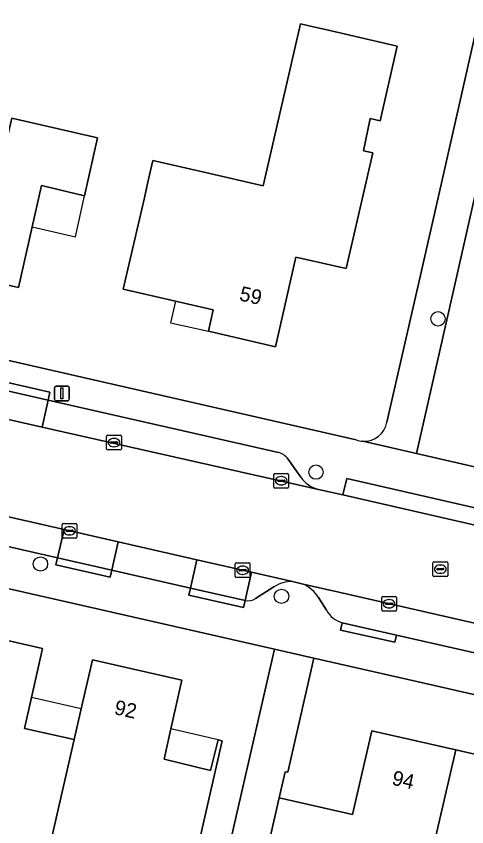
# Model space of a CAD drawing. Extents: x 159626 to 160723, y 388173 to 389416.
# Drawn here: x 160209.5 to 160240.2, y 388707.3 to 388762.4 of the extents above; entities that cross this region are included whole.
import ezdxf

# ---------------------------------------------------------------- set-up
doc = ezdxf.new("R2010")
doc.units = 0
for name, color, linetype in [('IMGEO_Boom', 7, 'Continuous'), ('IMGEO_Erf', 7, 'Continuous'), ('IMGEO_Kolk', 7, 'Continuous'), ('IMGEO_Lichtmast', 7, 'Continuous'), ('IMGEO_Pand', 7, 'Continuous'), ('IMGEO_Pand_nummerreeks', 7, 'Continuous'), ('IMGEO_Pand_overbouw', 7, 'Continuous'), ('IMGEO_Parkeervlak_open', 7, 'Continuous'), ('IMGEO_Rijbaan_lokaal_gesloten', 7, 'Continuous'), ('IMGEO_Rijbaan_lokaal_open', 7, 'Continuous'), ('IMGEO_Rioolput', 7, 'Continuous'), ('IMGEO_Voetpad_open', 7, 'Continuous')]:
    doc.layers.add(name, color=color, linetype=linetype)

msp = doc.modelspace()

# ---------------------------------------------------------------- linework, layer by layer
at = {"layer": 'IMGEO_Boom'}
for centre in [(160238.202, 388741.85), (160229.904, 388731.42), (160211.166, 388725.17), (160227.558, 388722.969)]:
    msp.add_circle(centre, 0.489, dxfattribs=at)
at = {"layer": 'IMGEO_Erf'}
for points in [[(160234.722, 388734.828), (160237.013, 388744.82), (160238.186, 388750), (160246.535, 388786.875)], [(160186.662, 388744.107), (160232.634, 388733.614)], [(160223.367, 388703.114), (160224.3, 388707.209), (160227.072, 388719.379), (160183.407, 388729.319), (160181.681, 388729.655), (160179.863, 388729.928)], [(160205.232, 388720.803), (160211.309, 388719.424), (160210.553, 388716.084), (160210.078, 388713.984), (160213.45, 388713.222), (160213.931, 388715.318), (160214.697, 388718.656), (160220.785, 388717.266), (160220.025, 388713.963), (160219.569, 388711.883), (160222.739, 388711.12), (160223.244, 388713.208), (160223.525, 388713.137), (160221.525, 388704.392)], [(160321.781, 388697.748), (160237.27, 388717.058), (160229.749, 388718.77), (160227.986, 388710.997), (160227.804, 388711.038), (160227.4, 388709.263), (160232.392, 388708.126), (160232.796, 388709.901), (160233.69, 388713.83), (160239.411, 388712.521), (160245.1, 388711.22), (160244.166, 388707.186)]]:
    msp.add_lwpolyline(points, dxfattribs=at)
for points in [[(160218.212, 388750), (160218.478, 388751.154), (160218.816, 388752.624), (160222.38, 388751.804), (160226.312, 388750.898), (160228.85, 388761.918), (160229.622, 388761.74), (160230.554, 388761.525), (160235.426, 388760.403), (160234.269, 388755.324), (160233.592, 388755.48), (160233.139, 388753.282), (160233.77, 388753.152), (160233.045, 388750), (160231.959, 388745.281), (160228.536, 388746.055), (160227.15, 388739.949), (160222.597, 388741), (160222.907, 388742.466), (160220.359, 388743.056), (160216.801, 388743.87)], [(160201.708, 388754.434), (160205.402, 388753.588), (160205.473, 388753.899), (160208.679, 388753.166), (160209.212, 388755.497), (160215.042, 388754.164), (160214.165, 388750.227), (160211.235, 388750.923), (160210.6, 388748.099), (160209.665, 388743.979), (160203.522, 388745.371), (160203.899, 388747.019), (160200.205, 388747.865), (160200.693, 388750)]]:
    msp.add_lwpolyline(points, close=True, dxfattribs=at)
for centre, radius, start, end in [((160233.177, 388735.083), 1.566, 266.9986, 350.6382), ((160233.176, 388735.078), 1.561, 249.6829, 267.0288)]:
    msp.add_arc(centre, radius, start, end, dxfattribs=at)
at = {"layer": 'IMGEO_Kolk'}
for p, q in [((160215.667, 388733.003), (160215.667, 388733.855)), ((160215.742, 388733.929), (160216.594, 388733.929)), ((160216.155, 388733.709), (160216.18, 388733.709)), ((160216.668, 388733.855), (160216.668, 388733.003)), ((160215.926, 388733.423), (160215.926, 388733.435)), ((160216.364, 388733.386), (160215.966, 388733.386)), ((160215.969, 388733.472), (160216.367, 388733.472)), ((160216.178, 388733.149), (160216.153, 388733.149)), ((160216.41, 388733.435), (160216.41, 388733.423)), ((160216.594, 388732.929), (160215.742, 388732.929)), ((160227.039, 388730.408), (160227.039, 388731.26)), ((160227.114, 388731.334), (160227.966, 388731.334)), ((160227.298, 388730.828), (160227.298, 388730.84)), ((160227.341, 388730.877), (160227.739, 388730.877)), ((160227.527, 388731.114), (160227.552, 388731.114)), ((160227.782, 388730.84), (160227.782, 388730.828)), ((160228.04, 388731.26), (160228.04, 388730.408)), ((160227.966, 388730.334), (160227.114, 388730.334)), ((160227.736, 388730.791), (160227.338, 388730.791)), ((160227.55, 388730.554), (160227.525, 388730.554)), ((160212.642, 388727.001), (160212.642, 388727.853)), ((160212.717, 388727.927), (160213.569, 388727.927)), ((160213.13, 388727.707), (160213.155, 388727.707)), ((160213.643, 388727.853), (160213.643, 388727.001)), ((160212.901, 388727.421), (160212.901, 388727.433)), ((160213.339, 388727.384), (160212.941, 388727.384)), ((160212.944, 388727.47), (160213.342, 388727.47)), ((160213.153, 388727.147), (160213.128, 388727.147)), ((160213.385, 388727.433), (160213.385, 388727.421)), ((160213.569, 388726.927), (160212.717, 388726.927)), ((160224.414, 388724.317), (160224.414, 388725.169)), ((160224.489, 388725.243), (160225.341, 388725.243)), ((160224.716, 388724.786), (160225.114, 388724.786)), ((160224.902, 388725.023), (160224.927, 388725.023)), ((160225.415, 388725.169), (160225.415, 388724.317)), ((160225.341, 388724.243), (160224.489, 388724.243)), ((160224.673, 388724.737), (160224.673, 388724.749)), ((160225.111, 388724.7), (160224.713, 388724.7)), ((160224.925, 388724.463), (160224.9, 388724.463)), ((160225.157, 388724.749), (160225.157, 388724.737)), ((160234.37, 388722.042), (160234.37, 388722.894)), ((160234.445, 388722.968), (160235.297, 388722.968)), ((160234.858, 388722.748), (160234.883, 388722.748)), ((160235.371, 388722.894), (160235.371, 388722.042)), ((160234.629, 388722.462), (160234.629, 388722.474)), ((160235.067, 388722.425), (160234.669, 388722.425)), ((160234.672, 388722.511), (160235.07, 388722.511)), ((160234.881, 388722.188), (160234.856, 388722.188)), ((160235.113, 388722.474), (160235.113, 388722.462)), ((160235.297, 388721.968), (160234.445, 388721.968))]:
    msp.add_line(p, q, dxfattribs=at)
for points in [[(160215.667, 388733.003), (160215.667, 388733.855)], [(160215.742, 388733.929), (160216.594, 388733.929)], [(160216.668, 388733.855), (160216.668, 388733.003)], [(160216.594, 388732.929), (160215.742, 388732.929)], [(160227.039, 388730.408), (160227.039, 388731.26)], [(160227.114, 388731.334), (160227.966, 388731.334)], [(160228.04, 388731.26), (160228.04, 388730.408)], [(160227.966, 388730.334), (160227.114, 388730.334)], [(160212.642, 388727.001), (160212.642, 388727.853)], [(160212.717, 388727.927), (160213.569, 388727.927)], [(160213.643, 388727.853), (160213.643, 388727.001)], [(160213.569, 388726.927), (160212.717, 388726.927)], [(160224.414, 388724.317), (160224.414, 388725.169)], [(160224.489, 388725.243), (160225.341, 388725.243)], [(160225.415, 388725.169), (160225.415, 388724.317)], [(160225.341, 388724.243), (160224.489, 388724.243)], [(160234.37, 388722.042), (160234.37, 388722.894)], [(160234.445, 388722.968), (160235.297, 388722.968)], [(160235.371, 388722.894), (160235.371, 388722.042)], [(160235.297, 388721.968), (160234.445, 388721.968)]]:
    msp.add_lwpolyline(points, dxfattribs=at)
for centre, radius, start, end in [((160215.744, 388733.853), 0.0765, 91.552, 178.448), ((160215.744, 388733.853), 0.0765, 91.552, 178.448), ((160216.592, 388733.853), 0.0765, 1.552, 88.448), ((160216.592, 388733.853), 0.0765, 1.552, 88.448), ((160215.966, 388733.432), 0.0403, 85.8775, 175.7526), ((160215.963, 388733.422), 0.0366, 178.938, 274.7102), ((160216.367, 388733.429), 0.043, 264.8664, 352.4533), ((160216.371, 388733.434), 0.0386, 1.7309, 96.639), ((160215.744, 388733.005), 0.0765, 181.552, 268.448), ((160215.744, 388733.005), 0.0765, 181.552, 268.448), ((160216.592, 388733.005), 0.0765, 271.552, 358.448), ((160216.592, 388733.005), 0.0765, 271.552, 358.448), ((160227.116, 388731.258), 0.0765, 91.552, 178.448), ((160227.116, 388731.258), 0.0765, 91.552, 178.448), ((160227.338, 388730.837), 0.0403, 85.8775, 175.7526), ((160227.335, 388730.827), 0.0366, 178.938, 274.7102), ((160227.739, 388730.834), 0.043, 264.8664, 352.4533), ((160227.743, 388730.839), 0.0386, 1.7309, 96.639), ((160227.964, 388731.258), 0.0765, 1.552, 88.448), ((160227.964, 388731.258), 0.0765, 1.552, 88.448), ((160227.116, 388730.41), 0.0765, 181.552, 268.448), ((160227.116, 388730.41), 0.0765, 181.552, 268.448), ((160227.964, 388730.41), 0.0765, 271.552, 358.448), ((160227.964, 388730.41), 0.0765, 271.552, 358.448), ((160212.719, 388727.851), 0.0765, 91.552, 178.448), ((160212.719, 388727.851), 0.0765, 91.552, 178.448), ((160213.567, 388727.851), 0.0765, 1.552, 88.448), ((160213.567, 388727.851), 0.0765, 1.552, 88.448), ((160212.719, 388727.003), 0.0765, 181.552, 268.448), ((160212.719, 388727.003), 0.0765, 181.552, 268.448), ((160212.941, 388727.43), 0.0403, 85.8775, 175.7526), ((160212.938, 388727.42), 0.0366, 178.938, 274.7102), ((160213.342, 388727.427), 0.043, 264.8664, 352.4533), ((160213.346, 388727.432), 0.0386, 1.7309, 96.639), ((160213.567, 388727.003), 0.0765, 271.552, 358.448), ((160213.567, 388727.003), 0.0765, 271.552, 358.448), ((160224.491, 388725.167), 0.0765, 91.552, 178.448), ((160224.491, 388725.167), 0.0765, 91.552, 178.448), ((160224.713, 388724.746), 0.0403, 85.8775, 175.7526), ((160225.118, 388724.748), 0.0386, 1.7309, 96.639), ((160225.339, 388725.167), 0.0765, 1.552, 88.448), ((160225.339, 388725.167), 0.0765, 1.552, 88.448), ((160224.491, 388724.319), 0.0765, 181.552, 268.448), ((160224.491, 388724.319), 0.0765, 181.552, 268.448), ((160224.71, 388724.736), 0.0366, 178.938, 274.7102), ((160225.114, 388724.743), 0.043, 264.8664, 352.4533), ((160225.339, 388724.319), 0.0765, 271.552, 358.448), ((160225.339, 388724.319), 0.0765, 271.552, 358.448), ((160234.447, 388722.892), 0.0765, 91.552, 178.448), ((160234.447, 388722.892), 0.0765, 91.552, 178.448), ((160235.295, 388722.892), 0.0765, 1.552, 88.448), ((160235.295, 388722.892), 0.0765, 1.552, 88.448), ((160234.447, 388722.044), 0.0765, 181.552, 268.448), ((160234.447, 388722.044), 0.0765, 181.552, 268.448), ((160234.669, 388722.471), 0.0403, 85.8775, 175.7526), ((160234.666, 388722.461), 0.0366, 178.938, 274.7102), ((160235.07, 388722.468), 0.043, 264.8664, 352.4533), ((160235.074, 388722.473), 0.0386, 1.7309, 96.639), ((160235.295, 388722.044), 0.0765, 271.552, 358.448), ((160235.295, 388722.044), 0.0765, 271.552, 358.448)]:
    msp.add_arc(centre, radius, start, end, dxfattribs=at)
for centre, major_axis, ratio, start_param, end_param in [((160216.154, 388733.429), (-0.387, 0.002), 0.722429, 4.712389, 7.853982), ((160216.179, 388733.429), (-0.39, 0.002), 0.717154, 1.570796, 4.712389), ((160227.526, 388730.834), (-0.387, 0.002), 0.722429, 4.712389, 7.853982), ((160227.551, 388730.834), (-0.39, 0.002), 0.717154, 1.570796, 4.712389), ((160213.129, 388727.427), (-0.387, 0.002), 0.722429, 4.712389, 7.853982), ((160213.154, 388727.427), (-0.39, 0.002), 0.717154, 1.570796, 4.712389), ((160224.901, 388724.743), (-0.387, 0.002), 0.722429, 4.712389, 7.853982), ((160224.926, 388724.743), (-0.39, 0.002), 0.717154, 1.570796, 4.712389), ((160234.857, 388722.468), (-0.387, 0.002), 0.722429, 4.712389, 7.853982), ((160234.882, 388722.468), (-0.39, 0.002), 0.717154, 1.570796, 4.712389)]:
    msp.add_ellipse(centre, major_axis=major_axis, ratio=ratio, start_param=start_param, end_param=end_param, dxfattribs=at)
at = {"layer": 'IMGEO_Lichtmast'}
for p, q in [((160212.127, 388736.374), (160212.127, 388737.174)), ((160212.127, 388737.174), (160212.127, 388736.374)), ((160212.227, 388737.274), (160213.017, 388737.274)), ((160213.017, 388737.274), (160212.227, 388737.274)), ((160213.117, 388737.174), (160213.117, 388736.374)), ((160213.117, 388736.374), (160213.117, 388737.174)), ((160213.017, 388736.274), (160212.227, 388736.274)), ((160212.227, 388736.274), (160213.017, 388736.274))]:
    msp.add_line(p, q, dxfattribs=at)
msp.add_lwpolyline([(160212.547, 388737.149), (160212.697, 388737.149), (160212.697, 388736.399), (160212.547, 388736.399), (160212.547, 388737.149)], dxfattribs=at)
for centre, start, end in [((160212.227, 388737.174), 90, 180), ((160212.227, 388737.174), 90, 180), ((160213.017, 388737.174), 0, 90), ((160213.017, 388737.174), 360, 90), ((160212.227, 388736.374), 180, 270), ((160212.227, 388736.374), 180, 270), ((160213.017, 388736.374), 270, 0), ((160213.017, 388736.374), 270, 0)]:
    msp.add_arc(centre, 0.1, start, end, dxfattribs=at)
at = {"layer": 'IMGEO_Pand'}
for points in [[(160233.77, 388753.152), (160233.139, 388753.282), (160233.592, 388755.48), (160234.269, 388755.324), (160235.426, 388760.403), (160230.554, 388761.525), (160229.622, 388761.74), (160228.85, 388761.918), (160226.312, 388750.898), (160222.38, 388751.804), (160218.816, 388752.624), (160218.478, 388751.154), (160218.212, 388750), (160216.801, 388743.87), (160220.359, 388743.056), (160222.907, 388742.466), (160222.597, 388741), (160227.15, 388739.949), (160228.536, 388746.055), (160231.959, 388745.281), (160233.045, 388750)], [(160214.165, 388750.227), (160215.042, 388754.164), (160209.212, 388755.497), (160208.679, 388753.166), (160205.473, 388753.899), (160205.402, 388753.588), (160201.708, 388754.434), (160200.693, 388750), (160200.205, 388747.865), (160203.899, 388747.019), (160203.522, 388745.371), (160209.665, 388743.979), (160210.6, 388748.099), (160211.235, 388750.923)], [(160213.45, 388713.222), (160210.078, 388713.984), (160210.553, 388716.084), (160211.309, 388719.424), (160205.232, 388720.803), (160204.479, 388717.507), (160203.99, 388715.368), (160203.012, 388711.086), (160203.159, 388711.052), (160206.774, 388710.226), (160206.239, 388707.888), (160205.731, 388705.666), (160208.592, 388701.238), (160208.943, 388701.124), (160209.218, 388702.195), (160210.98, 388701.792), (160211.459, 388703.887), (160212.026, 388706.564), (160211.928, 388706.586)], [(160223.525, 388713.137), (160223.244, 388713.208), (160222.739, 388711.12), (160219.569, 388711.883), (160220.025, 388713.963), (160220.785, 388717.266), (160214.697, 388718.656), (160213.931, 388715.318), (160213.45, 388713.222), (160211.928, 388706.586), (160212.026, 388706.564), (160211.459, 388703.887), (160215.202, 388703.03), (160215.813, 388705.698), (160216.651, 388705.507), (160221.525, 388704.392)], [(160239.411, 388712.521), (160233.69, 388713.83), (160232.796, 388709.901), (160232.392, 388708.126), (160227.4, 388709.263), (160225.341, 388700.225), (160231.578, 388698.805), (160232.916, 388699.692), (160233.152, 388700.775), (160233.73, 388703.316), (160237.101, 388702.549)], [(160237.101, 388702.549), (160240.482, 388701.78), (160239.904, 388699.239), (160245.641, 388697.934), (160247.535, 388706.406), (160244.166, 388707.186), (160245.1, 388711.22), (160239.411, 388712.521)]]:
    msp.add_lwpolyline(points, close=True, dxfattribs=at)
at = {"layer": 'IMGEO_Pand_overbouw'}
for points in [[(160214.165, 388750.227), (160211.235, 388750.923), (160210.6, 388748.099), (160213.544, 388747.439)], [(160220.359, 388743.056), (160220.005, 388741.575), (160222.597, 388741), (160222.907, 388742.466)], [(160213.931, 388715.318), (160210.553, 388716.084), (160210.078, 388713.984), (160213.45, 388713.222)], [(160223.244, 388713.208), (160220.025, 388713.963), (160219.569, 388711.883), (160222.739, 388711.12)]]:
    msp.add_lwpolyline(points, close=True, dxfattribs=at)
at = {"layer": 'IMGEO_Parkeervlak_open'}
for points in [[(160211.696, 388736.31), (160207.987, 388737.153), (160207.553, 388735.321), (160211.28, 388734.481)], [(160212.768, 388727.514), (160207.181, 388728.788), (160206.742, 388726.865), (160212.324, 388725.595)], [(160216.45, 388726.674), (160212.768, 388727.514), (160212.324, 388725.595), (160216.011, 388724.754)], [(160221.807, 388725.453), (160216.45, 388726.674), (160216.011, 388724.754), (160216.013, 388724.754), (160221.37, 388723.533)], [(160225.52, 388724.606), (160221.807, 388725.453), (160221.37, 388723.533), (160225.081, 388722.687)]]:
    msp.add_lwpolyline(points, close=True, dxfattribs=at)
for points in [[(160211.696, 388736.31), (160211.28, 388734.481), (160230.065, 388730.247)], [(160227.347, 388732.748), (160211.696, 388736.31)], [(160228.876, 388731.081), (160227.997, 388732.315)], [(160228.297, 388723.973), (160225.52, 388724.606), (160225.081, 388722.687)], [(160231.462, 388723.248), (160229.021, 388723.807)], [(160225.792, 388722.823), (160227.036, 388723.608)], [(160231.681, 388721.166), (160235.38, 388720.33), (160246.805, 388717.749), (160247.241, 388719.647), (160231.462, 388723.248)], [(160230.077, 388722.88), (160230.621, 388722.026)]]:
    msp.add_lwpolyline(points, dxfattribs=at)
for centre, radius, start, end in [((160227.109, 388731.687), 1.088, 35.2876, 77.373), ((160230.538, 388732.186), 1.996, 213.6201, 256.286), ((160228.267, 388721.716), 2.257, 89.2381, 123.0483), ((160228.052, 388721.638), 2.376, 31.523, 65.921), ((160225.256, 388723.698), 1.026, 260.1678, 301.4897), ((160232.191, 388722.878), 1.786, 208.4784, 253.4154)]:
    msp.add_arc(centre, radius, start, end, dxfattribs=at)
at = {"layer": 'IMGEO_Rijbaan_lokaal_gesloten'}
msp.add_lwpolyline([(160244.089, 388727.051), (160231.719, 388729.878), (160230.065, 388730.247), (160211.28, 388734.481), (160207.553, 388735.321), (160192.873, 388738.63), (160187.729, 388739.79), (160186.385, 388733.53), (160194.236, 388731.738), (160197.887, 388730.906), (160203.464, 388729.635), (160207.181, 388728.788), (160212.768, 388727.514), (160216.45, 388726.674), (160221.807, 388725.453), (160225.52, 388724.606), (160228.297, 388723.973), (160229.021, 388723.807), (160231.462, 388723.248), (160247.241, 388719.647)], dxfattribs=at)
at = {"layer": 'IMGEO_Rijbaan_lokaal_open'}
msp.add_lwpolyline([(160252.345, 388777.916), (160247.25, 388779.082), (160240.666, 388750), (160239.37, 388744.275), (160236.732, 388732.697), (160241.762, 388731.537), (160244.339, 388742.931), (160245.957, 388750)], close=True, dxfattribs=at)
at = {"layer": 'IMGEO_Rioolput'}
for p, q in [((160237.932, 388725.32), (160238.784, 388725.32)), ((160237.857, 388724.394), (160237.857, 388725.246)), ((160238.116, 388724.814), (160238.116, 388724.826)), ((160238.554, 388724.777), (160238.156, 388724.777)), ((160238.159, 388724.863), (160238.557, 388724.863)), ((160238.345, 388725.1), (160238.37, 388725.1)), ((160238.6, 388724.826), (160238.6, 388724.814)), ((160238.858, 388725.246), (160238.858, 388724.394)), ((160238.784, 388724.32), (160237.932, 388724.32)), ((160238.368, 388724.54), (160238.343, 388724.54))]:
    msp.add_line(p, q, dxfattribs=at)
for points in [[(160237.932, 388725.32), (160238.784, 388725.32)], [(160237.857, 388724.394), (160237.857, 388725.246)], [(160238.858, 388725.246), (160238.858, 388724.394)], [(160238.784, 388724.32), (160237.932, 388724.32)]]:
    msp.add_lwpolyline(points, dxfattribs=at)
for centre, radius, start, end in [((160237.934, 388725.244), 0.0765, 91.552, 178.448), ((160237.934, 388725.244), 0.0765, 91.552, 178.448), ((160238.782, 388725.244), 0.0765, 1.552, 88.448), ((160238.782, 388725.244), 0.0765, 1.552, 88.448), ((160238.156, 388724.823), 0.0403, 85.8775, 175.7526), ((160238.153, 388724.813), 0.0366, 178.938, 274.7102), ((160238.557, 388724.82), 0.043, 264.8664, 352.4533), ((160238.561, 388724.825), 0.0386, 1.7309, 96.639), ((160237.934, 388724.396), 0.0765, 181.552, 268.448), ((160237.934, 388724.396), 0.0765, 181.552, 268.448), ((160238.782, 388724.396), 0.0765, 271.552, 358.448), ((160238.782, 388724.396), 0.0765, 271.552, 358.448)]:
    msp.add_arc(centre, radius, start, end, dxfattribs=at)
for centre, major_axis, ratio, start_param, end_param in [((160238.344, 388724.82), (-0.387, 0.002), 0.722429, 4.712389, 7.853982), ((160238.369, 388724.82), (-0.39, 0.002), 0.717154, 1.570796, 4.712389)]:
    msp.add_ellipse(centre, major_axis=major_axis, ratio=ratio, start_param=start_param, end_param=end_param, dxfattribs=at)
at = {"layer": 'IMGEO_Voetpad_open'}
for points in [[(160246.535, 388786.875), (160238.186, 388750), (160237.013, 388744.82), (160234.722, 388734.828)], [(160233.095, 388733.519), (160236.732, 388732.697), (160239.37, 388744.275), (160240.666, 388750), (160247.25, 388779.082)], [(160232.634, 388733.614), (160186.662, 388744.107)], [(160187.322, 388741.856), (160188.156, 388741.666), (160188.276, 388742.193), (160193.434, 388741.012), (160193.311, 388740.493), (160207.987, 388737.153), (160208.117, 388737.698), (160211.81, 388736.85), (160211.696, 388736.31), (160227.347, 388732.748)], [(160236.732, 388732.697), (160233.095, 388733.519)], [(160225.081, 388722.687), (160224.97, 388722.2), (160221.258, 388723.045), (160221.37, 388723.533), (160216.013, 388724.754), (160215.9, 388724.267), (160212.213, 388725.108), (160212.324, 388725.595), (160206.742, 388726.865), (160206.631, 388726.377), (160202.914, 388727.223), (160203.025, 388727.71), (160197.447, 388728.98), (160197.336, 388728.492), (160193.643, 388729.33), (160193.754, 388729.817), (160191.078, 388730.424), (160181.115, 388732.553)], [(160230.065, 388730.247), (160231.719, 388729.878), (160232.003, 388730.992), (160244.371, 388728.159), (160246.042, 388730.589), (160241.762, 388731.537), (160236.732, 388732.697)], [(160227.997, 388732.315), (160228.876, 388731.081)], [(160174.144, 388731.086), (160179.863, 388729.928), (160181.681, 388729.655), (160183.407, 388729.319), (160227.072, 388719.379), (160229.749, 388718.77), (160237.27, 388717.058), (160321.781, 388697.748), (160325.989, 388696.807)], [(160229.021, 388723.807), (160228.297, 388723.973)], [(160227.036, 388723.608), (160225.792, 388722.823)], [(160230.621, 388722.026), (160230.077, 388722.88)], [(160317.901, 388701.629), (160307.972, 388703.897), (160307.871, 388703.42), (160301.244, 388704.929), (160301.333, 388705.414), (160289.592, 388708.096), (160289.502, 388707.619), (160282.881, 388709.142), (160282.993, 388709.603), (160271.843, 388712.15), (160271.74, 388711.669), (160265.096, 388713.191), (160265.213, 388713.665), (160253.461, 388716.246), (160253.351, 388715.758), (160246.695, 388717.262), (160246.805, 388717.749), (160235.38, 388720.33), (160235.27, 388719.842), (160231.571, 388720.678), (160231.681, 388721.166)]]:
    msp.add_lwpolyline(points, dxfattribs=at)
for points in [[(160211.696, 388736.31), (160211.81, 388736.85), (160208.117, 388737.698), (160207.987, 388737.153)], [(160231.719, 388729.878), (160244.089, 388727.051), (160244.371, 388728.159), (160232.003, 388730.992)], [(160212.324, 388725.595), (160212.213, 388725.108), (160215.9, 388724.267), (160216.013, 388724.754), (160216.011, 388724.754)], [(160221.37, 388723.533), (160221.258, 388723.045), (160224.97, 388722.2), (160225.081, 388722.687)], [(160231.681, 388721.166), (160231.571, 388720.678), (160235.27, 388719.842), (160235.38, 388720.33)], [(160229.749, 388718.77), (160227.072, 388719.379), (160224.3, 388707.209), (160223.367, 388703.114), (160216.868, 388674.586), (160214.412, 388663.806), (160217.052, 388663.19), (160219.408, 388673.465), (160221.263, 388681.555), (160223.772, 388692.499), (160225.194, 388698.701), (160225.004, 388698.744), (160225.341, 388700.225), (160227.4, 388709.263), (160227.804, 388711.038), (160227.986, 388710.997)]]:
    msp.add_lwpolyline(points, close=True, dxfattribs=at)
for centre, radius, start, end in [((160233.177, 388735.083), 1.566, 266.9986, 350.6382), ((160233.176, 388735.078), 1.561, 249.6829, 267.0288), ((160227.109, 388731.687), 1.088, 35.2876, 77.373), ((160230.538, 388732.186), 1.996, 213.6201, 256.286), ((160228.267, 388721.716), 2.257, 89.2381, 123.0483), ((160228.052, 388721.638), 2.376, 31.523, 65.921), ((160225.256, 388723.698), 1.026, 260.1678, 301.4897), ((160232.191, 388722.878), 1.786, 208.4784, 253.4154)]:
    msp.add_arc(centre, radius, start, end, dxfattribs=at)

# ---------------------------------------------------------------- texts
at = {"layer": 'IMGEO_Pand_nummerreeks'}
for s, rotation, p in [('59', 346.9996, (160224.636, 388743.116)), ('92', 347.1428, (160216.125, 388714.965)), ('94', 347.1142, (160235.006, 388710.164))]:
    msp.add_text(s, height=1, rotation=rotation, dxfattribs=at).set_placement(p)

doc.saveas('drawing.dxf')
